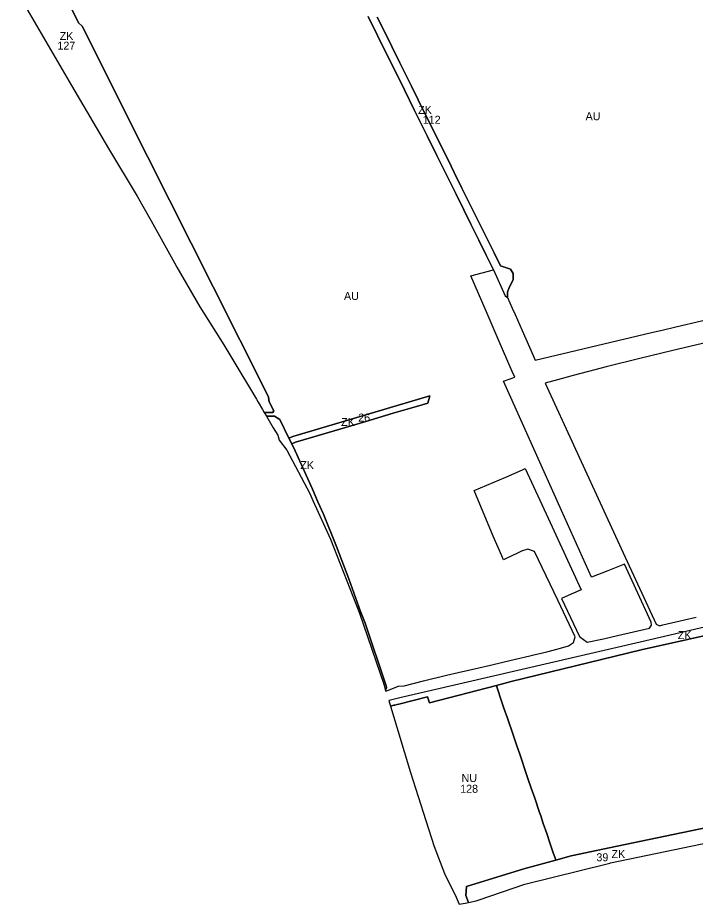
# Model space of a CAD drawing. Extents: x -521939 to -516426, y -1197857 to -1189551.
# Drawn here: x -521507 to -520661, y -1192801 to -1191694 of the extents above; entities that cross this region are included whole.
import ezdxf

# ---------------------------------------------------------------- set-up
doc = ezdxf.new("R2010")
doc.units = 0
for name, color, linetype in [('90710013', 7, 'Continuous'), ('90710023', 7, 'Continuous'), ('90730023', 7, 'Continuous'), ('90750013', 7, 'Continuous'), ('90760013', 7, 'Continuous'), ('ID_navrh', 7, 'Continuous')]:
    doc.layers.add(name, color=color, linetype=linetype)

msp = doc.modelspace()

# ---------------------------------------------------------------- linework, layer by layer
at = {"layer": '90710013'}
for points in [[(-521168.5, -1192218.83), (-521179.7, -1192195.78), (-521186.69, -1192191.46), (-521196.65, -1192191.4), (-521188.01, -1192205.95), (-521182.15, -1192215.19), (-521180.6, -1192221.68), (-521171.09, -1192234.03), (-521142.49, -1192288.12), (-521138.47, -1192296.86), (-521116.32, -1192345.01), (-521080.21, -1192437.67), (-521049.85, -1192526.39), (-521047.81, -1192533.73), (-521047.12, -1192532.78), (-521046.61, -1192531.37), (-521046.49, -1192529.87), (-521046.78, -1192528.4), (-521073.06, -1192450.07), (-521078.83, -1192435.69), (-521093.46, -1192394.8), (-521108.98, -1192354.24), (-521125.38, -1192314.03), (-521132.13, -1192298.44), (-521138.87, -1192282.81), (-521160.78, -1192234.71), (-521164.96, -1192226.12), (-521168.5, -1192218.83)], [(-520429.27, -1192404.08), (-520729.45, -1192473.76), (-521029.64, -1192543.45), (-521034.64, -1192544.61), (-521039.64, -1192545.77), (-521041.54, -1192546.21), (-521043.45, -1192546.66), (-521041.32, -1192553.76), (-521037.14, -1192552.7), (-521036.09, -1192552.43), (-521033.12, -1192551.66), (-521030.87, -1192551.11), (-520995.13, -1192542.04), (-520992.77, -1192549.69), (-520908.99, -1192527.86)], [(-520908.99, -1192527.86), (-520890.49, -1192523.04), (-520728.34, -1192483.53), (-520554.6, -1192444.53)]]:
    msp.add_lwpolyline(points, dxfattribs=at)
at = {"layer": '90710023'}
for points in [[(-521507.47, -1191662.82), (-521475.16, -1191718.42), (-521440.41, -1191778.22), (-521394.07, -1191856.97), (-521358.15, -1191916.77), (-521340.67, -1191947.49), (-521311.39, -1192000), (-521308.38, -1192005.41), (-521279.68, -1192054.79), (-521250, -1192102.48), (-521238.5, -1192120.96), (-521209.18, -1192170.31), (-521207.02, -1192173.96), (-521201.6, -1192183.07), (-521199.33, -1192186.9), (-521188.6, -1192186.94), (-521187.37, -1192184.96), (-521193.11, -1192173.56), (-521193.86, -1192167.63), (-521196.15, -1192163.08), (-521263.12, -1192029.99), (-521345.06, -1191867.15), (-521427, -1191704.31), (-521431.33, -1191700.15), (-521440.4, -1191682.13)], [(-521069.59, -1191692.15), (-521045.95, -1191739.73), (-521033.33, -1191765.25), (-521024.18, -1191783.72), (-521011.95, -1191808.58), (-520995.26, -1191842.12), (-520983.63, -1191865.68), (-520959.52, -1191914.15), (-520949.74, -1191933.88), (-520941.03, -1191951.61), (-520931.19, -1191971.43), (-520921.84, -1191990.28), (-520912.71, -1192008.61)], [(-520912.71, -1192008.61), (-520898.22, -1192040.98), (-520895.11, -1192043.42), (-520895.08, -1192040.13), (-520895.06, -1192036.66), (-520893.18, -1192030.83), (-520888.16, -1192021.2), (-520888.12, -1192013.43), (-520891.41, -1192007.81), (-520897.64, -1192005.71), (-520904.09, -1192003.54), (-520912.07, -1191987.5), (-520919.89, -1191971.66), (-520928.16, -1191955.01), (-520941.86, -1191927.51), (-520952.13, -1191906.66), (-520961.83, -1191887.02), (-520965.82, -1191878.99), (-520981.65, -1191847.19), (-520989.64, -1191831.01), (-521006.81, -1191796.39), (-521015.3, -1191779.24), (-521025.6, -1191758.4), (-521029.7, -1191750.25), (-521039.79, -1191729.8), (-521052.87, -1191703.37), (-521058, -1191692.92)], [(-521168.5, -1192218.83), (-521164.96, -1192226.12), (-521160.1, -1192224.03), (-521140.15, -1192218.12), (-521111.98, -1192209.79), (-521097.8, -1192205.47), (-521072.45, -1192198.08), (-521057.45, -1192193.65), (-521038.14, -1192187.92), (-521020.52, -1192182.75), (-521008.84, -1192179.25), (-520994.96, -1192175.05), (-520992.3, -1192166.01), (-521163.51, -1192216.7), (-521168.5, -1192218.83)], [(-520592.85, -1192713.96), (-520593.8, -1192709.96), (-520596.04, -1192695.13), (-520758.3, -1192728.9), (-520815.45, -1192740.8), (-520834.88, -1192746.05), (-520874.84, -1192756.86), (-520946.38, -1192779.22), (-520947.19, -1192790.27), (-520944.08, -1192798.91), (-520934.56, -1192796.95), (-520930.47, -1192795.56), (-520873.66, -1192776.25), (-520770.76, -1192750.7), (-520767.25, -1192749.83), (-520766.41, -1192749.65), (-520607.67, -1192716.44), (-520592.85, -1192713.96)]]:
    msp.add_lwpolyline(points, dxfattribs=at)
at = {"layer": '90730023'}
msp.add_lwpolyline([(-520908.99, -1192527.86), (-520992.77, -1192549.69), (-520995.13, -1192542.04), (-521030.87, -1192551.11), (-521033.12, -1192551.66), (-521036.09, -1192552.43), (-521037.14, -1192552.7), (-521041.32, -1192553.76), (-521016.55, -1192636.53), (-520997.18, -1192696.65), (-520986.7, -1192729.16), (-520974.15, -1192762.68), (-520959.24, -1192792.44), (-520955.72, -1192801.31), (-520948.03, -1192799.73), (-520944.08, -1192798.91), (-520947.19, -1192790.27), (-520946.38, -1192779.22), (-520874.84, -1192756.86), (-520834.88, -1192746.05), (-520835.3, -1192744.66), (-520837.96, -1192736.86), (-520840.49, -1192729.47), (-520842.13, -1192724.66), (-520846.21, -1192712.75), (-520850.47, -1192700.26), (-520853.74, -1192690.71), (-520855.19, -1192686.47), (-520861.2, -1192668.88), (-520866, -1192654.84), (-520869.28, -1192645.23), (-520871.37, -1192639.12), (-520879.59, -1192615.06), (-520884.03, -1192602.07), (-520888.34, -1192589.46), (-520895.43, -1192568.72), (-520899.67, -1192556.33), (-520903.57, -1192544.89), (-520907.44, -1192533.58), (-520908.21, -1192530.72), (-520908.99, -1192527.86)], dxfattribs=at)
at = {"layer": '90750013'}
for points in [[(-521440.4, -1191682.13), (-521431.33, -1191700.15), (-521427, -1191704.31), (-521345.06, -1191867.15), (-521263.12, -1192029.99), (-521196.15, -1192163.08), (-521193.86, -1192167.63), (-521193.11, -1192173.56), (-521187.37, -1192184.96), (-521188.6, -1192186.94), (-521199.33, -1192186.9), (-521196.65, -1192191.4), (-521186.69, -1192191.46), (-521179.7, -1192195.78), (-521168.5, -1192218.83), (-521163.51, -1192216.7), (-520992.3, -1192166.01), (-520994.96, -1192175.05), (-521008.84, -1192179.25), (-521020.52, -1192182.75), (-521038.14, -1192187.92), (-521057.45, -1192193.65), (-521072.45, -1192198.08), (-521097.8, -1192205.47), (-521111.98, -1192209.79), (-521140.15, -1192218.12), (-521160.1, -1192224.03), (-521164.96, -1192226.12), (-521160.78, -1192234.71), (-521138.87, -1192282.81), (-521132.13, -1192298.44), (-521125.38, -1192314.03), (-521108.98, -1192354.24), (-521093.46, -1192394.8), (-521078.83, -1192435.69), (-521073.06, -1192450.07), (-521046.78, -1192528.4), (-521046.49, -1192529.87), (-521046.61, -1192531.37), (-521047.12, -1192532.78), (-521047.81, -1192533.73), (-521047.48, -1192534.92), (-521031.5, -1192528.93), (-521024.31, -1192528.23), (-521000.32, -1192522.3), (-520971.48, -1192515.16), (-520956.94, -1192511.77), (-520931.25, -1192505.82), (-520916.4, -1192502.38), (-520901.21, -1192498.82), (-520885.36, -1192495.15), (-520867.3, -1192490.96), (-520862.36, -1192489.81), (-520846.11, -1192486.03), (-520831.91, -1192482.32), (-520819, -1192478.55), (-520812.86, -1192474.26), (-520810.52, -1192467.28), (-520832.42, -1192421.41), (-520861.55, -1192360.4), (-520869.79, -1192357.78), (-520877.84, -1192360.32), (-520883.66, -1192363.12), (-520896.8, -1192369.44), (-520900.36, -1192371.15), (-520902.52, -1192366.01), (-520912.95, -1192341.61), (-520936.99, -1192284.54), (-520897.45, -1192267.89), (-520876.44, -1192258.58), (-520872.99, -1192256.99), (-520844.37, -1192319.13), (-520803.15, -1192408.61), (-520815.5, -1192414.01), (-520827.84, -1192419.41), (-520816.49, -1192443.18), (-520805.14, -1192466.95), (-520800.34, -1192470.38), (-520795.54, -1192473.81), (-520775.03, -1192469.66), (-520757.59, -1192465.66), (-520717.93, -1192456.26), (-520715.38, -1192452.8), (-520715.58, -1192448.99), (-520749.03, -1192376.55), (-520769.7, -1192384.57), (-520790.37, -1192392.59), (-520790.38, -1192392.59), (-520827.64, -1192309.54), (-520900.27, -1192147.67), (-520886.27, -1192142.96), (-520889.52, -1192135.58), (-520907.04, -1192095.09), (-520921.91, -1192060.3), (-520941.16, -1192016.12), (-520912.71, -1192008.61), (-520921.84, -1191990.28), (-520931.19, -1191971.43), (-520941.03, -1191951.61), (-520949.74, -1191933.88), (-520959.52, -1191914.15), (-520983.63, -1191865.68), (-520995.26, -1191842.12), (-521011.95, -1191808.58), (-521024.18, -1191783.72), (-521033.33, -1191765.25), (-521045.95, -1191739.73), (-521069.59, -1191692.15)], [(-521058, -1191692.92), (-521052.87, -1191703.37), (-521039.79, -1191729.8), (-521029.7, -1191750.25), (-521025.6, -1191758.4), (-521015.3, -1191779.24), (-521006.81, -1191796.39), (-520989.64, -1191831.01), (-520981.65, -1191847.19), (-520965.82, -1191878.99), (-520961.83, -1191887.02), (-520952.13, -1191906.66), (-520941.86, -1191927.51), (-520928.16, -1191955.01), (-520919.89, -1191971.66), (-520912.07, -1191987.5), (-520904.09, -1192003.54), (-520897.64, -1192005.71), (-520891.41, -1192007.81), (-520888.12, -1192013.43), (-520888.16, -1192021.2), (-520893.18, -1192030.83), (-520895.06, -1192036.66), (-520895.08, -1192040.13), (-520895.11, -1192043.42), (-520889.36, -1192056.46), (-520885.79, -1192064.54), (-520877.05, -1192084.34), (-520863.21, -1192115.71), (-520860.7, -1192121.39), (-520715.06, -1192087.15), (-520701.85, -1192084.04), (-520684.93, -1192080.06), (-520620.5, -1192064.91)], [(-520644.57, -1192098.88), (-520690.33, -1192109.89), (-520729.94, -1192119.3), (-520771.74, -1192129.79), (-520786.26, -1192133.58), (-520813.01, -1192140.6), (-520828.27, -1192144.69), (-520848.21, -1192150.07), (-520772.3, -1192315.26), (-520748.17, -1192367.77), (-520709.22, -1192451.33), (-520705.38, -1192453.34), (-520700.9, -1192452.29), (-520674.16, -1192446.1), (-520659.49, -1192442.68)]]:
    msp.add_lwpolyline(points, dxfattribs=at)
at = {"layer": '90760013'}
for points in [[(-520554.6, -1192444.53), (-520728.34, -1192483.53), (-520890.49, -1192523.04), (-520908.99, -1192527.86)], [(-520908.99, -1192527.86), (-520908.21, -1192530.72), (-520907.44, -1192533.58), (-520903.57, -1192544.89), (-520899.67, -1192556.33), (-520895.43, -1192568.72), (-520888.34, -1192589.46), (-520884.03, -1192602.07), (-520879.59, -1192615.06), (-520871.37, -1192639.12), (-520869.28, -1192645.23), (-520866, -1192654.84), (-520861.2, -1192668.88), (-520855.19, -1192686.47), (-520853.74, -1192690.71), (-520850.47, -1192700.26), (-520846.21, -1192712.75), (-520842.13, -1192724.66), (-520840.49, -1192729.47), (-520837.96, -1192736.86), (-520835.3, -1192744.66), (-520834.88, -1192746.05), (-520815.45, -1192740.8), (-520758.3, -1192728.9), (-520596.04, -1192695.13)]]:
    msp.add_lwpolyline(points, dxfattribs=at)

# ---------------------------------------------------------------- texts
at = {"layer": '90710013'}
for p in [(-521154.23, -1192257.67), (-520682.33, -1192469.97)]:
    msp.add_text('ZK', height=10, rotation=360, dxfattribs=at).set_placement(p)
at = {"layer": '90710023'}
for rotation, p in [(0, (-521454.97, -1191721.53)), (0, (-521006.96, -1191813.81)), (360, (-521103.21, -1192203.74)), (360, (-520765.22, -1192743.59))]:
    msp.add_text('ZK', height=10, rotation=rotation, dxfattribs=at).set_placement(p)
at = {"layer": '90730023'}
msp.add_text('NU', height=10, rotation=360, dxfattribs=at).set_placement((-520952.66, -1192648.57))
at = {"layer": '90750013'}
for p in [(-520797.63, -1191821.73), (-521099.6, -1192046.32)]:
    msp.add_text('AU', height=10, rotation=360, dxfattribs=at).set_placement(p)
at = {"layer": 'ID_navrh'}
for s, rotation, p in [('127', 360, (-521457.83, -1191733.62)), ('112', 0, (-521001.16, -1191826.15)), ('26', 0, (-521081.86, -1192198.26)), ('128', 360, (-520954.38, -1192662)), ('39', 0, (-520784.08, -1192747.58))]:
    msp.add_text(s, height=10, rotation=rotation, dxfattribs=at).set_placement(p)

doc.saveas('drawing.dxf')
